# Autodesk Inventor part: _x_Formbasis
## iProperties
Created: 2005-11
Part Number: _x_Formbasis
Document SubType Name: Modeling
Designer: IMA/Frank
Manufacturer: Standard
Standards Organization: Custom
Author: IMA/Frank
